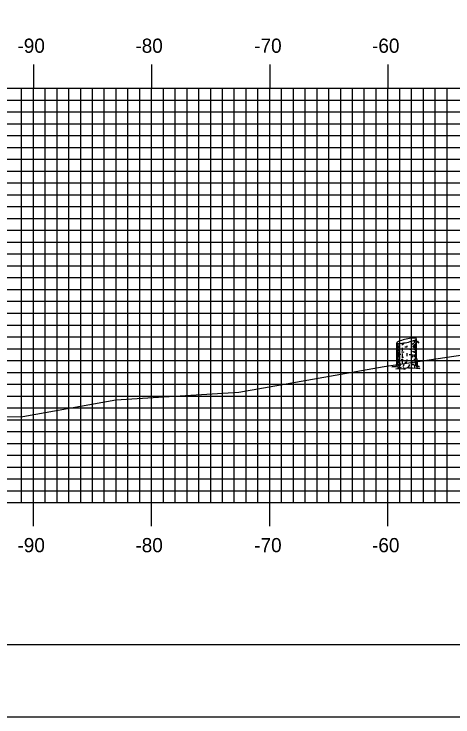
# Model space of a CAD drawing. Extents: x 852542 to 852886, y 364366 to 364586.
# Drawn here: x 852616.5 to 852653.7, y 364365.7 to 364425.1 of the extents above; entities that cross this region are included whole.
import ezdxf

# ---------------------------------------------------------------- set-up
doc = ezdxf.new("R2010")
doc.units = 0
for name, color, linetype in [('BORDER', 7, 'Continuous'), ('H_V ANNOTATION', 7, 'Continuous'), ('M_Trees_Conifer_Pay', 7, 'Continuous'), ('MAJOR', 7, 'Continuous'), ('MINOR', 7, 'Continuous'), ('PLOT BOUNDARY', 7, 'Continuous'), ('S_Roadway_Centerline', 7, 'Continuous')]:
    doc.layers.add(name, color=color, linetype=linetype)

msp = doc.modelspace()

# ---------------------------------------------------------------- linework, layer by layer
at = {"layer": 'BORDER'}
msp.add_lwpolyline([(852558.578, 364371.787), (852878.578, 364371.787), (852878.578, 364581.787), (852558.578, 364581.787)], close=True, dxfattribs=at)
at = {"layer": 'M_Trees_Conifer_Pay'}
for p, q in [((852650.52, 364397.551), (852650.52, 364397.388)), ((852650.591, 364395.976), (852650.591, 364397.623)), ((852648.927, 364395.566), (852648.927, 364397.288)), ((852648.974, 364397.25), (852648.974, 364396.779)), ((852649.033, 364397.239), (852649.033, 364397.141)), ((852649.033, 364397.067), (852649.033, 364396.863)), ((852649.158, 364397.231), (852649.158, 364396.999)), ((852649.158, 364396.958), (852649.158, 364396.884)), ((852649.378, 364397.252), (852649.378, 364397.084)), ((852649.783, 364397.02), (852649.783, 364396.925)), ((852650.174, 364397.294), (852650.174, 364397.094)), ((852650.174, 364397.036), (852650.174, 364396.948)), ((852650.402, 364397.49), (852650.402, 364397.267)), ((852650.402, 364397.178), (852650.402, 364397.131)), ((852650.459, 364396.995), (852650.408, 364396.935)), ((852650.52, 364397.32), (852650.52, 364397.192)), ((852650.52, 364397.005), (852650.52, 364396.669)), ((852648.974, 364396.715), (852648.974, 364396.406)), ((852648.974, 364396.359), (852648.974, 364395.867)), ((852649.033, 364396.805), (852649.033, 364396.606)), ((852649.033, 364396.559), (852649.033, 364396.223)), ((852649.158, 364396.481), (852649.158, 364396.342)), ((852649.378, 364396.847), (852649.378, 364396.61)), ((852649.378, 364396.365), (852649.378, 364396.213)), ((852649.783, 364396.406), (852649.783, 364396.332)), ((852650.174, 364396.6), (852650.174, 364396.495)), ((852650.402, 364396.795), (852650.402, 364396.664)), ((852650.402, 364396.553), (852650.402, 364396.443)), ((852650.52, 364396.633), (852650.52, 364396.47)), ((852650.52, 364396.423), (852650.52, 364396.206)), ((852648.974, 364395.813), (852648.974, 364395.566)), ((852649.033, 364396.169), (852649.033, 364396.034)), ((852649.033, 364395.935), (852649.033, 364395.556)), ((852649.158, 364396.07), (852649.158, 364395.929)), ((852649.378, 364396.169), (852649.378, 364395.996)), ((852649.783, 364396.307), (852649.783, 364396.159)), ((852649.783, 364395.867), (852649.783, 364395.714)), ((852650.174, 364396.128), (852650.174, 364395.982)), ((852650.402, 364396.307), (852650.402, 364396.166)), ((852650.402, 364395.939), (852650.402, 364395.766)), ((852650.52, 364396.175), (852650.52, 364396.101)), ((852650.52, 364396.061), (852650.52, 364395.887)), ((852649.158, 364395.667), (852649.158, 364395.572)), ((852649.158, 364395.173), (852649.321, 364395.236)), ((852649.378, 364395.719), (852649.378, 364395.566)), ((852649.595, 364395.108), (852649.469, 364395.173)), ((852650.174, 364395.75), (852650.174, 364395.661))]:
    msp.add_line(p, q, dxfattribs=at)
for points in [[(852650.375, 364397.084), (852650.344, 364396.999), (852650.34, 364396.931), (852650.371, 364396.868)], [(852650.408, 364397.121), (852650.445, 364397.047), (852650.492, 364397.104), (852650.55, 364397.172), (852650.642, 364397.366), (852650.707, 364397.413), (852650.737, 364397.419)], [(852650.422, 364396.868), (852650.459, 364396.995), (852650.523, 364397.11), (852650.554, 364397.178), (852650.623, 364397.324)], [(852650.637, 364397.354), (852650.712, 364397.362), (852650.785, 364397.263)], [(852649.106, 364396.593), (852649.1, 364396.689), (852649.144, 364396.666), (852649.144, 364396.571)], [(852650.591, 364395.976), (852650.642, 364395.714), (852650.659, 364395.44), (852650.716, 364395.315), (852650.852, 364395.284), (852650.622, 364395.247), (852650.622, 364395.247), (852650.628, 364395.2), (852650.875, 364395.105), (852650.601, 364395.122), (852650.245, 364395.142), (852649.924, 364395.131), (852649.93, 364395.214), (852649.782, 364395.131), (852649.595, 364395.108), (852649.619, 364395.041), (852649.352, 364395.084), (852649.131, 364395.057), (852648.838, 364395.074), (852649.127, 364395.131), (852649.158, 364395.173), (852648.995, 364395.231), (852648.758, 364395.241), (852648.518, 364395.241), (852648.859, 364395.299), (852648.901, 364395.379), (852648.927, 364395.566)], [(852650.245, 364396.194), (852650.258, 364396.118), (852650.305, 364396.128), (852650.292, 364396.295)], [(852650.517, 364395.834), (852650.523, 364395.688), (852650.57, 364395.62), (852650.581, 364395.42)], [(852648.975, 364395.519), (852648.954, 364395.44), (852648.934, 364395.346)], [(852649.053, 364395.498), (852649.059, 364395.383), (852649.006, 364395.294), (852648.995, 364395.231)], [(852649.216, 364395.525), (852649.216, 364395.393), (852649.127, 364395.294)], [(852649.442, 364395.284), (852649.51, 364395.379), (852649.537, 364395.519)], [(852649.93, 364395.214), (852650.004, 364395.356), (852650.014, 364395.457)], [(852650.181, 364395.583), (852650.191, 364395.457), (852650.266, 364395.414)], [(852650.459, 364395.194), (852650.445, 364395.332), (852650.371, 364395.461)], [(852650.418, 364395.688), (852650.492, 364395.583), (852650.497, 364395.41), (852650.622, 364395.247)]]:
    msp.add_lwpolyline(points, dxfattribs=at)
for centre, radius, start, end in [((852650.783, 364392.52), 5.179, 101.7194, 108.05939), ((852650.783, 364392.52), 5.179, 95.37941, 101.7194), ((852650.373, 364396.878), 0.802, 79.2194, 95.37941), ((852650.092, 364398.229), 0.802, 288.05939, 304.2194), ((852650.476, 364397.419), 0.251, 71.05013, 79.2194), ((852650.402, 364397.773), 0.251, 304.2194, 312.38868), ((852650.53, 364397.579), 0.0817, 56.7194, 71.05013), ((852650.516, 364397.648), 0.0817, 312.38868, 326.7194), ((852650.546, 364397.603), 0.0527, 46.92298, 56.7194), ((852650.561, 364397.619), 0.0314, 34.2194, 46.92298), ((852650.54, 364397.633), 0.0527, 326.7194, 336.51582), ((852650.565, 364397.622), 0.0264, 23.40735, 34.2194), ((852650.568, 364397.623), 0.0226, 11.7194, 23.40735), ((852650.56, 364397.624), 0.0314, 336.51582, 349.2194), ((852650.568, 364397.623), 0.0226, 0.03145, 11.7194), ((852650.565, 364397.623), 0.0264, 349.2194, 0.03145), ((852648.959, 364397.109), 0.0334, 163.94846, 180), ((852648.959, 364397.109), 0.0334, 180, 196.05154), ((852648.954, 364397.287), 0.0264, 169.2194, 180.03145), ((852648.95, 364397.287), 0.0226, 180.03145, 191.7194), ((852648.97, 364397.112), 0.0441, 196.05154, 210), ((852648.958, 364397.286), 0.0314, 156.51582, 169.2194), ((852648.95, 364397.287), 0.0226, 191.7194, 203.40735), ((852648.953, 364397.289), 0.0264, 203.40735, 214.2194), ((852648.978, 364397.278), 0.0527, 146.7194, 156.51582), ((852648.957, 364397.292), 0.0314, 214.2194, 226.92298), ((852648.985, 364397.121), 0.0624, 210, 228.74941), ((852649.002, 364397.262), 0.0817, 132.38868, 146.7194), ((852648.972, 364397.307), 0.0527, 226.92298, 236.7194), ((852648.988, 364397.331), 0.0817, 236.7194, 251.05013), ((852649.058, 364397.204), 0.172, 228.74941, 240), ((852649.116, 364397.137), 0.251, 124.2194, 132.38868), ((852649.043, 364397.491), 0.251, 251.05013, 259.2194), ((852649.257, 364397.549), 0.571, 240, 240.33672), ((852649.426, 364396.682), 0.802, 108.05939, 124.2194), ((852649.146, 364398.032), 0.802, 259.2194, 275.37941), ((852649.257, 364397.549), 0.571, 246.85973, 257.98457), ((852648.735, 364402.39), 5.179, 275.37941, 281.7194), ((852649.759, 364401.3), 4.124, 264.6955, 266.73309), ((852649.758, 364401.067), 4.124, 268.07512, 270), ((852648.735, 364402.39), 5.179, 281.7194, 288.05939), ((852649.758, 364401.067), 4.124, 275.78493, 277.05584), ((852649.759, 364401.3), 4.124, 276.23804, 278.1032), ((852650.26, 364397.782), 0.571, 278.1032, 284.36665), ((852650.26, 364397.936), 0.571, 284.43166, 292.41325), ((852650.26, 364397.782), 0.571, 297.0237, 300), ((852650.459, 364397.591), 0.172, 300, 311.25059), ((852650.459, 364397.437), 0.172, 300, 311.25059), ((852650.532, 364397.509), 0.0624, 311.25059, 330), ((852650.532, 364397.354), 0.0624, 311.25059, 330), ((852650.548, 364397.5), 0.0441, 330, 343.94846), ((852650.548, 364397.345), 0.0441, 330, 343.94846), ((852650.558, 364397.497), 0.0334, 343.94846, 354.21506), ((852650.558, 364397.342), 0.0334, 343.94846, 354.21506), ((852648.959, 364396.663), 0.0334, 163.94846, 180), ((852648.959, 364396.663), 0.0334, 180, 196.05154), ((852648.959, 364396.453), 0.0334, 163.94846, 180), ((852648.959, 364396.453), 0.0334, 180, 196.05154), ((852648.97, 364396.666), 0.0441, 196.05154, 210), ((852648.97, 364396.456), 0.0441, 196.05154, 210), ((852648.985, 364396.675), 0.0624, 210, 228.74941), ((852648.985, 364396.465), 0.0624, 210, 228.74941), ((852649.058, 364396.757), 0.172, 228.74941, 240), ((852649.058, 364396.547), 0.172, 228.74941, 240), ((852649.257, 364397.102), 0.571, 240, 240.33672), ((852649.257, 364396.892), 0.571, 240, 246.85973), ((852649.258, 364397.338), 0.571, 240, 247.05866), ((852649.758, 364400.62), 4.124, 264.08098, 266.66759), ((852649.758, 364401.067), 4.124, 270, 270.35814), ((852649.759, 364400.856), 4.124, 273.70524, 275.95043), ((852649.758, 364400.62), 4.124, 277.61247, 278.1032), ((852650.259, 364397.102), 0.571, 278.1032, 286.92962), ((852650.26, 364397.338), 0.571, 284.44928, 297.04285), ((852650.259, 364397.102), 0.571, 297.18959, 300), ((852650.259, 364396.892), 0.571, 297.18959, 300), ((852650.458, 364396.757), 0.172, 300, 311.25059), ((852650.458, 364396.547), 0.172, 300, 311.25059), ((852650.53, 364396.675), 0.0624, 311.25059, 330), ((852650.53, 364396.465), 0.0624, 311.25059, 330), ((852650.546, 364396.666), 0.0441, 330, 343.94846), ((852650.546, 364396.456), 0.0441, 330, 343.94846), ((852650.556, 364396.663), 0.0334, 343.94846, 354.21506), ((852650.556, 364396.453), 0.0334, 343.94846, 354.21506), ((852650.558, 364396.898), 0.0334, 343.94846, 354.21506), ((852648.959, 364396.216), 0.0334, 163.94846, 180), ((852648.959, 364396.216), 0.0334, 180, 196.05154), ((852648.959, 364396.018), 0.0334, 163.94846, 180), ((852648.959, 364395.822), 0.0334, 163.94846, 180), ((852648.959, 364395.822), 0.0334, 180, 196.05154), ((852648.97, 364396.219), 0.0441, 196.05154, 210), ((852648.97, 364395.825), 0.0441, 196.05154, 210), ((852648.985, 364396.228), 0.0624, 210, 228.74941), ((852648.985, 364395.835), 0.0624, 210, 228.74941), ((852649.058, 364396.31), 0.172, 228.74941, 240), ((852649.058, 364395.917), 0.172, 228.74941, 240), ((852649.257, 364396.656), 0.571, 240, 246.85973), ((852649.246, 364396.464), 0.571, 241.23686, 248.02677), ((852649.257, 364396.262), 0.571, 240, 246.85973), ((852649.257, 364396.892), 0.571, 259.27072, 261.8968), ((852649.758, 364400.41), 4.124, 261.8968, 263.14738), ((852649.758, 364399.975), 4.124, 263.49906, 265.83975), ((852649.758, 364400.173), 4.124, 264.71603, 266.31934), ((852649.758, 364400.41), 4.124, 270, 270.35814), ((852649.758, 364400.41), 4.124, 273.14934, 275.45691), ((852650.259, 364396.656), 0.571, 285.39827, 297.18959), ((852650.259, 364396.458), 0.571, 289.29072, 300), ((852650.458, 364396.113), 0.172, 300, 311.25059), ((852650.53, 364396.03), 0.0624, 311.25059, 330), ((852650.546, 364396.021), 0.0441, 330, 343.94846), ((852650.556, 364396.018), 0.0334, 343.94846, 354.21506), ((852648.959, 364395.602), 0.0334, 163.94846, 180), ((852648.959, 364395.602), 0.0334, 180, 196.05154), ((852648.97, 364395.605), 0.0441, 196.05154, 210), ((852648.985, 364395.614), 0.0624, 210, 228.74941), ((852649.058, 364395.697), 0.172, 228.74941, 240), ((852649.257, 364396.042), 0.571, 240, 244.53138), ((852649.758, 364399.56), 4.124, 262.44379, 263.51202), ((852649.758, 364399.78), 4.124, 267.81166, 270), ((852649.758, 364399.78), 4.124, 270, 270.13279), ((852649.758, 364399.78), 4.124, 275.78493, 276.78961), ((852649.758, 364399.56), 4.124, 277.36842, 278.1032), ((852650.259, 364396.042), 0.571, 278.1032, 281.63703), ((852650.259, 364396.262), 0.571, 288.50673, 297.27208), ((852650.458, 364395.697), 0.172, 300, 311.25059), ((852650.53, 364395.614), 0.0624, 311.25059, 330), ((852650.546, 364395.605), 0.0441, 330, 343.94846), ((852650.556, 364395.602), 0.0334, 343.94846, 354.21506)]:
    msp.add_arc(centre, radius, start, end, dxfattribs=at)
at = {"layer": 'MAJOR'}
for p, q in [((852618.178, 364420.791), (852618.178, 364418.787)), ((852628.178, 364420.791), (852628.178, 364418.787)), ((852638.178, 364420.791), (852638.178, 364418.787)), ((852648.178, 364420.791), (852648.178, 364418.787)), ((852568.178, 364418.787), (852848.178, 364418.787)), ((852568.178, 364418.787), (852848.178, 364418.787)), ((852618.178, 364383.787), (852618.178, 364418.787)), ((852628.178, 364383.787), (852628.178, 364418.787)), ((852638.178, 364383.787), (852638.178, 364418.787)), ((852648.178, 364383.787), (852648.178, 364418.787)), ((852568.178, 364413.787), (852848.178, 364413.787)), ((852568.178, 364408.787), (852848.178, 364408.787)), ((852568.178, 364403.787), (852848.178, 364403.787)), ((852568.178, 364398.787), (852848.178, 364398.787)), ((852568.178, 364393.787), (852848.178, 364393.787)), ((852568.178, 364388.787), (852848.178, 364388.787)), ((852568.178, 364383.787), (852848.178, 364383.787)), ((852568.178, 364383.787), (852848.178, 364383.787)), ((852618.178, 364381.783), (852618.178, 364383.787)), ((852628.178, 364381.783), (852628.178, 364383.787)), ((852638.178, 364381.783), (852638.178, 364383.787)), ((852648.178, 364381.783), (852648.178, 364383.787))]:
    msp.add_line(p, q, dxfattribs=at)
at = {"layer": 'MINOR'}
for p, q in [((852617.178, 364383.787), (852617.178, 364418.787)), ((852619.178, 364383.787), (852619.178, 364418.787)), ((852620.178, 364383.787), (852620.178, 364418.787)), ((852621.178, 364383.787), (852621.178, 364418.787)), ((852622.178, 364383.787), (852622.178, 364418.787)), ((852623.178, 364383.787), (852623.178, 364418.787)), ((852624.178, 364383.787), (852624.178, 364418.787)), ((852625.178, 364383.787), (852625.178, 364418.787)), ((852626.178, 364383.787), (852626.178, 364418.787)), ((852627.178, 364383.787), (852627.178, 364418.787)), ((852629.178, 364383.787), (852629.178, 364418.787)), ((852630.178, 364383.787), (852630.178, 364418.787)), ((852631.178, 364383.787), (852631.178, 364418.787)), ((852632.178, 364383.787), (852632.178, 364418.787)), ((852633.178, 364383.787), (852633.178, 364418.787)), ((852634.178, 364383.787), (852634.178, 364418.787)), ((852635.178, 364383.787), (852635.178, 364418.787)), ((852636.178, 364383.787), (852636.178, 364418.787)), ((852637.178, 364383.787), (852637.178, 364418.787)), ((852639.178, 364383.787), (852639.178, 364418.787)), ((852640.178, 364383.787), (852640.178, 364418.787)), ((852641.178, 364383.787), (852641.178, 364418.787)), ((852642.178, 364383.787), (852642.178, 364418.787)), ((852643.178, 364383.787), (852643.178, 364418.787)), ((852644.178, 364383.787), (852644.178, 364418.787)), ((852645.178, 364383.787), (852645.178, 364418.787)), ((852646.178, 364383.787), (852646.178, 364418.787)), ((852647.178, 364383.787), (852647.178, 364418.787)), ((852649.178, 364383.787), (852649.178, 364418.787)), ((852650.178, 364383.787), (852650.178, 364418.787)), ((852651.178, 364383.787), (852651.178, 364418.787)), ((852652.178, 364383.787), (852652.178, 364418.787)), ((852653.178, 364383.787), (852653.178, 364418.787)), ((852568.178, 364417.787), (852848.178, 364417.787)), ((852568.178, 364416.787), (852848.178, 364416.787)), ((852568.178, 364415.787), (852848.178, 364415.787)), ((852568.178, 364414.787), (852848.178, 364414.787)), ((852568.178, 364412.787), (852848.178, 364412.787)), ((852568.178, 364411.787), (852848.178, 364411.787)), ((852568.178, 364410.787), (852848.178, 364410.787)), ((852568.178, 364409.787), (852848.178, 364409.787)), ((852568.178, 364407.787), (852848.178, 364407.787)), ((852568.178, 364406.787), (852848.178, 364406.787)), ((852568.178, 364405.787), (852848.178, 364405.787)), ((852568.178, 364404.787), (852848.178, 364404.787)), ((852568.178, 364402.787), (852848.178, 364402.787)), ((852568.178, 364401.787), (852848.178, 364401.787)), ((852568.178, 364400.787), (852848.178, 364400.787)), ((852568.178, 364399.787), (852848.178, 364399.787)), ((852568.178, 364397.787), (852848.178, 364397.787)), ((852568.178, 364396.787), (852848.178, 364396.787)), ((852568.178, 364395.787), (852848.178, 364395.787)), ((852568.178, 364394.787), (852848.178, 364394.787)), ((852568.178, 364392.787), (852848.178, 364392.787)), ((852568.178, 364391.787), (852848.178, 364391.787)), ((852568.178, 364390.787), (852848.178, 364390.787)), ((852568.178, 364389.787), (852848.178, 364389.787)), ((852568.178, 364387.787), (852848.178, 364387.787)), ((852568.178, 364386.787), (852848.178, 364386.787)), ((852568.178, 364385.787), (852848.178, 364385.787)), ((852568.178, 364384.787), (852848.178, 364384.787))]:
    msp.add_line(p, q, dxfattribs=at)
at = {"layer": 'PLOT BOUNDARY'}
msp.add_lwpolyline([(852542.392, 364365.669), (852882.392, 364365.669), (852882.392, 364585.669), (852542.392, 364585.669)], close=True, dxfattribs=at)
at = {"layer": 'S_Roadway_Centerline'}
msp.add_lwpolyline([(852568.178, 364389.653), (852574.124, 364389.68), (852579.335, 364389.626), (852588.614, 364389.629), (852597.954, 364389.902), (852600.269, 364390.493), (852604.34, 364390.409), (852612.17, 364390.986), (852617.284, 364391.045), (852625.147, 364392.472), (852635.572, 364393.111), (852637.65, 364393.473), (852647.868, 364395.294), (852669.738, 364398.532), (852672.306, 364398.911), (852673.814, 364399.054), (852688.559, 364399.681), (852700.745, 364402.23)], dxfattribs=at)

# ---------------------------------------------------------------- texts
at = {"layer": 'H_V ANNOTATION'}
for s, p in [('-90', (852616.83, 364421.787)), ('-80', (852626.808, 364421.787)), ('-70', (852636.862, 364421.787)), ('-60', (852646.83, 364421.787)), ('-90', (852616.83, 364379.587)), ('-80', (852626.808, 364379.587)), ('-70', (852636.862, 364379.587)), ('-60', (852646.83, 364379.587))]:
    msp.add_text(s, height=1.2, dxfattribs=at).set_placement(p)

doc.saveas('drawing.dxf')
